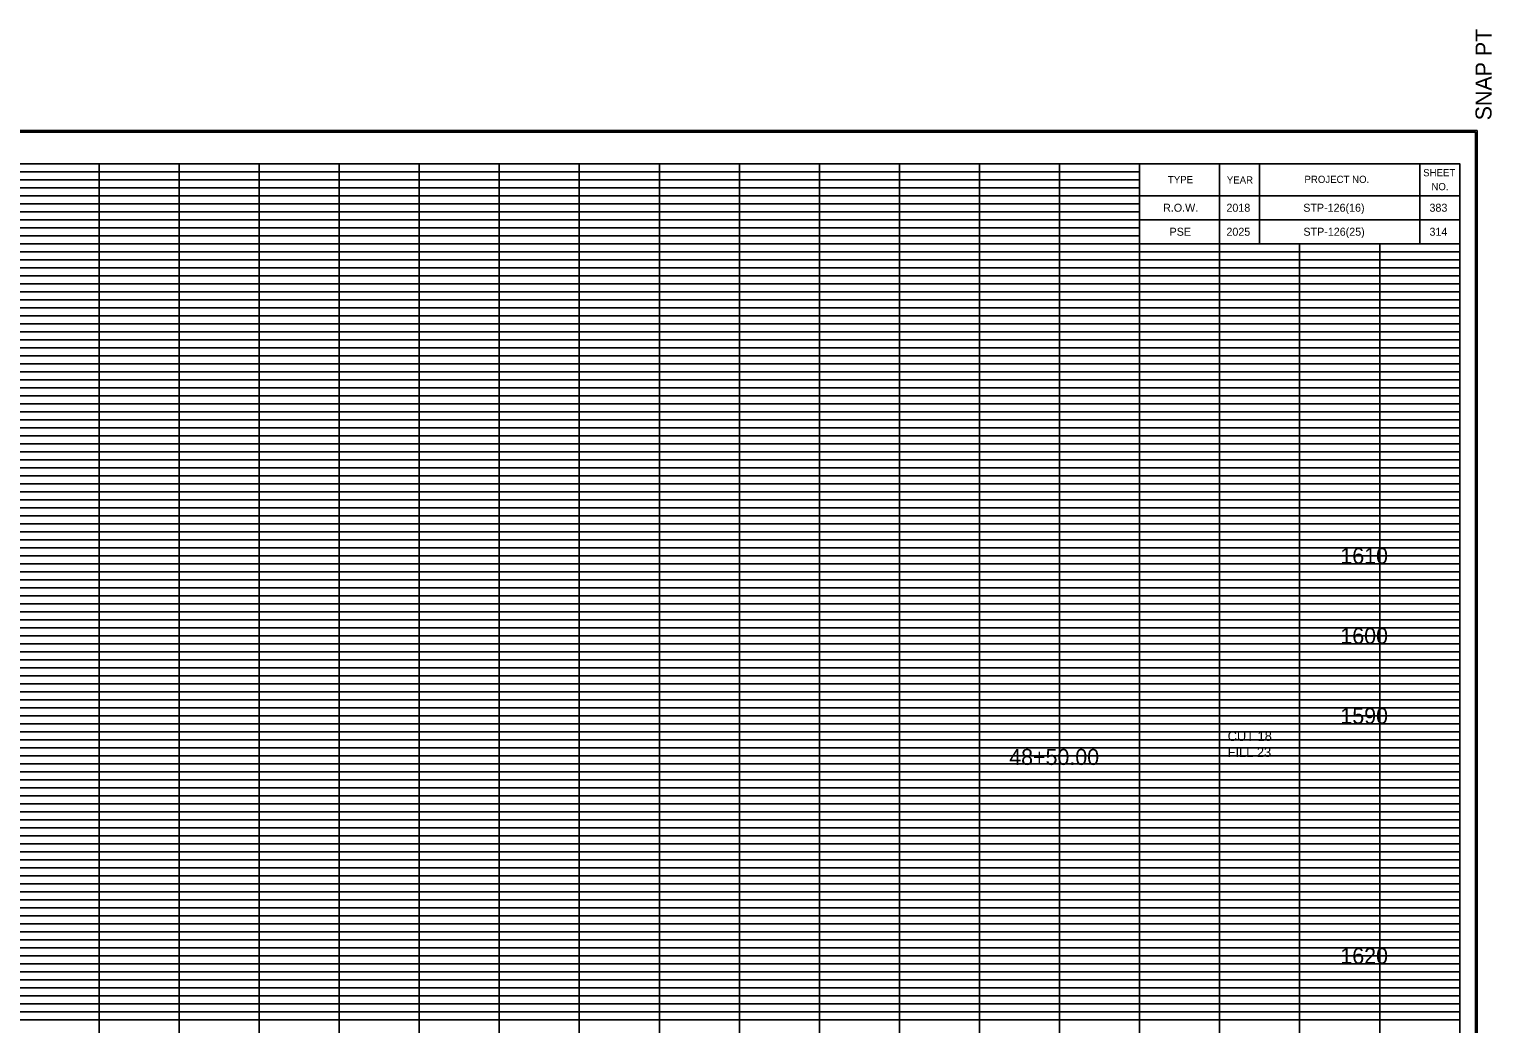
# Model space of a CAD drawing. Extents: x 980 to 1324, y 978 to 1497.
# Drawn here: x 1141.3 to 1324, y 1102.5 to 1226.8 of the extents above; entities that cross this region are included whole.
import ezdxf

# ---------------------------------------------------------------- set-up
doc = ezdxf.new("R2010")
doc.units = 0
for name, color, linetype in [('DESIGN - SCRATCH - User 1', 7, 'Continuous'), ('DESIGN - SHEET - Corner Text', 7, 'Continuous'), ('DESIGN - SHEET - Light Grid', 7, 'Continuous'), ('DESIGN - SHEET - Linework', 7, 'Continuous'), ('DESIGN - SHEET - Plot Shape', 7, 'Continuous'), ('DESIGN - TYPICAL - Text', 7, 'Continuous')]:
    doc.layers.add(name, color=color, linetype=linetype)

# ---------------------------------------------------------------- blocks, each defined once
blk = doc.blocks.new('XSTSHT')
at = {"layer": 'DESIGN - SCRATCH - User 1'}
for p, q in [((28.5, 20.45), (28.5, 20.45)), ((29.24, 20.45), (29.24, 20.45)), ((30.49, 20.45), (30.49, 20.45)), ((31.74, 20.45), (31.74, 20.45)), ((28.5, 20.15), (28.5, 20.15)), ((29.24, 20.15), (29.24, 20.15)), ((30.49, 20.15), (30.49, 20.15)), ((31.74, 20.15), (31.74, 20.15))]:
    blk.add_line(p, q, dxfattribs=at)
at = {"layer": 'DESIGN - SHEET - Light Grid'}
for p, q in [((8, 20.9), (16, 20.9)), ((16, 20.9), (24, 20.9)), ((24, 20.9), (28, 20.9)), ((8, 20.8), (16, 20.8)), ((8, 20.7), (16, 20.7)), ((16, 20.8), (24, 20.8)), ((16, 20.7), (24, 20.7)), ((24, 20.8), (28, 20.8)), ((24, 20.7), (28, 20.7)), ((8, 20.6), (16, 20.6)), ((8, 20.5), (16, 20.5)), ((16, 20.6), (24, 20.6)), ((16, 20.5), (24, 20.5)), ((24, 20.6), (28, 20.6)), ((24, 20.5), (28, 20.5)), ((8, 20.4), (16, 20.4)), ((8, 20.3), (16, 20.3)), ((16, 20.4), (24, 20.4)), ((16, 20.3), (24, 20.3)), ((24, 20.4), (28, 20.4)), ((24, 20.3), (28, 20.3)), ((8, 20.2), (16, 20.2)), ((8, 20.1), (16, 20.1)), ((16, 20.2), (24, 20.2)), ((16, 20.1), (24, 20.1)), ((24, 20.2), (28, 20.2)), ((24, 20.1), (28, 20.1)), ((8, 19.9), (16, 19.9)), ((8, 19.8), (16, 19.8)), ((16, 19.9), (24, 19.9)), ((16, 19.8), (24, 19.8)), ((24, 19.9), (32, 19.9)), ((24, 19.8), (32, 19.8)), ((8, 19.7), (16, 19.7)), ((8, 19.6), (16, 19.6)), ((16, 19.7), (24, 19.7)), ((16, 19.6), (24, 19.6)), ((24, 19.7), (32, 19.7)), ((24, 19.6), (32, 19.6)), ((8, 19.5), (16, 19.5)), ((8, 19.4), (16, 19.4)), ((16, 19.5), (24, 19.5)), ((16, 19.4), (24, 19.4)), ((24, 19.5), (32, 19.5)), ((24, 19.4), (32, 19.4)), ((8, 19.3), (16, 19.3)), ((8, 19.2), (16, 19.2)), ((16, 19.3), (24, 19.3)), ((16, 19.2), (24, 19.2)), ((24, 19.3), (32, 19.3)), ((24, 19.2), (32, 19.2)), ((8, 19.1), (16, 19.1)), ((16, 19.1), (24, 19.1)), ((24, 19.1), (32, 19.1)), ((8, 18.9), (16, 18.9)), ((16, 18.9), (24, 18.9)), ((24, 18.9), (32, 18.9)), ((8, 18.8), (16, 18.8)), ((8, 18.7), (16, 18.7)), ((16, 18.8), (24, 18.8)), ((16, 18.7), (24, 18.7)), ((24, 18.8), (32, 18.8)), ((24, 18.7), (32, 18.7)), ((8, 18.6), (16, 18.6)), ((8, 18.5), (16, 18.5)), ((16, 18.6), (24, 18.6)), ((16, 18.5), (24, 18.5)), ((24, 18.6), (32, 18.6)), ((24, 18.5), (32, 18.5)), ((8, 18.4), (16, 18.4)), ((8, 18.3), (16, 18.3)), ((16, 18.4), (24, 18.4)), ((16, 18.3), (24, 18.3)), ((24, 18.4), (32, 18.4)), ((24, 18.3), (32, 18.3)), ((8, 18.2), (16, 18.2)), ((8, 18.1), (16, 18.1)), ((16, 18.2), (24, 18.2)), ((16, 18.1), (24, 18.1)), ((24, 18.2), (32, 18.2)), ((24, 18.1), (32, 18.1)), ((8, 17.9), (16, 17.9)), ((8, 17.8), (16, 17.8)), ((16, 17.9), (24, 17.9)), ((16, 17.8), (24, 17.8)), ((24, 17.9), (32, 17.9)), ((24, 17.8), (32, 17.8)), ((8, 17.7), (16, 17.7)), ((8, 17.6), (16, 17.6)), ((16, 17.7), (24, 17.7)), ((16, 17.6), (24, 17.6)), ((24, 17.7), (32, 17.7)), ((24, 17.6), (32, 17.6)), ((8, 17.5), (16, 17.5)), ((8, 17.4), (16, 17.4)), ((16, 17.5), (24, 17.5)), ((16, 17.4), (24, 17.4)), ((24, 17.5), (32, 17.5)), ((24, 17.4), (32, 17.4)), ((8, 17.3), (16, 17.3)), ((8, 17.2), (16, 17.2)), ((16, 17.3), (24, 17.3)), ((16, 17.2), (24, 17.2)), ((24, 17.3), (32, 17.3)), ((24, 17.2), (32, 17.2)), ((8, 17.1), (16, 17.1)), ((16, 17.1), (24, 17.1)), ((24, 17.1), (32, 17.1)), ((8, 16.9), (16, 16.9)), ((16, 16.9), (24, 16.9)), ((24, 16.9), (32, 16.9)), ((8, 16.8), (16, 16.8)), ((8, 16.7), (16, 16.7)), ((16, 16.8), (24, 16.8)), ((16, 16.7), (24, 16.7)), ((24, 16.8), (32, 16.8)), ((24, 16.7), (32, 16.7)), ((8, 16.6), (16, 16.6)), ((8, 16.5), (16, 16.5)), ((16, 16.6), (24, 16.6)), ((16, 16.5), (24, 16.5)), ((24, 16.6), (32, 16.6)), ((24, 16.5), (32, 16.5)), ((8, 16.4), (16, 16.4)), ((8, 16.3), (16, 16.3)), ((16, 16.4), (24, 16.4)), ((16, 16.3), (24, 16.3)), ((24, 16.4), (32, 16.4)), ((24, 16.3), (32, 16.3)), ((8, 16.2), (16, 16.2)), ((8, 16.1), (16, 16.1)), ((16, 16.2), (24, 16.2)), ((16, 16.1), (24, 16.1)), ((24, 16.2), (32, 16.2)), ((24, 16.1), (32, 16.1)), ((8, 15.9), (16, 15.9)), ((16, 15.9), (24, 15.9)), ((24, 15.9), (32, 15.9)), ((8, 15.8), (16, 15.8)), ((16, 15.8), (24, 15.8)), ((24, 15.8), (32, 15.8)), ((8, 15.7), (16, 15.7)), ((8, 15.6), (16, 15.6)), ((16, 15.7), (24, 15.7)), ((16, 15.6), (24, 15.6)), ((24, 15.7), (32, 15.7)), ((24, 15.6), (32, 15.6)), ((8, 15.5), (16, 15.5)), ((8, 15.4), (16, 15.4)), ((16, 15.5), (24, 15.5)), ((16, 15.4), (24, 15.4)), ((24, 15.5), (32, 15.5)), ((24, 15.4), (32, 15.4)), ((8, 15.3), (16, 15.3)), ((8, 15.2), (16, 15.2)), ((16, 15.3), (24, 15.3)), ((16, 15.2), (24, 15.2)), ((24, 15.3), (32, 15.3)), ((24, 15.2), (32, 15.2)), ((8, 15.1), (16, 15.1)), ((16, 15.1), (24, 15.1)), ((24, 15.1), (32, 15.1)), ((8, 14.9), (16, 14.9)), ((16, 14.9), (24, 14.9)), ((24, 14.9), (32, 14.9)), ((8, 14.8), (16, 14.8)), ((8, 14.7), (16, 14.7)), ((16, 14.8), (24, 14.8)), ((16, 14.7), (24, 14.7)), ((24, 14.8), (32, 14.8)), ((24, 14.7), (32, 14.7)), ((8, 14.6), (16, 14.6)), ((8, 14.5), (16, 14.5)), ((16, 14.6), (24, 14.6)), ((16, 14.5), (24, 14.5)), ((24, 14.6), (32, 14.6)), ((24, 14.5), (32, 14.5)), ((8, 14.4), (16, 14.4)), ((8, 14.3), (16, 14.3)), ((16, 14.4), (24, 14.4)), ((16, 14.3), (24, 14.3)), ((24, 14.4), (32, 14.4)), ((24, 14.3), (32, 14.3)), ((8, 14.2), (16, 14.2)), ((8, 14.1), (16, 14.1)), ((16, 14.2), (24, 14.2)), ((16, 14.1), (24, 14.1)), ((24, 14.2), (32, 14.2)), ((24, 14.1), (32, 14.1)), ((8, 13.9), (16, 13.9)), ((16, 13.9), (24, 13.9)), ((24, 13.9), (32, 13.9)), ((8, 13.8), (16, 13.8)), ((16, 13.8), (24, 13.8)), ((24, 13.8), (32, 13.8)), ((8, 13.7), (16, 13.7)), ((8, 13.6), (16, 13.6)), ((16, 13.7), (24, 13.7)), ((16, 13.6), (24, 13.6)), ((24, 13.7), (32, 13.7)), ((24, 13.6), (32, 13.6)), ((8, 13.5), (16, 13.5)), ((8, 13.4), (16, 13.4)), ((16, 13.5), (24, 13.5)), ((16, 13.4), (24, 13.4)), ((24, 13.5), (32, 13.5)), ((24, 13.4), (32, 13.4)), ((8, 13.3), (16, 13.3)), ((8, 13.2), (16, 13.2)), ((16, 13.3), (24, 13.3)), ((16, 13.2), (24, 13.2)), ((24, 13.3), (32, 13.3)), ((24, 13.2), (32, 13.2)), ((8, 13.1), (16, 13.1)), ((16, 13.1), (24, 13.1)), ((24, 13.1), (32, 13.1)), ((8, 12.9), (16, 12.9)), ((8, 12.8), (16, 12.8)), ((16, 12.9), (24, 12.9)), ((16, 12.8), (24, 12.8)), ((24, 12.9), (32, 12.9)), ((24, 12.8), (32, 12.8)), ((8, 12.7), (16, 12.7)), ((16, 12.7), (24, 12.7)), ((24, 12.7), (32, 12.7)), ((8, 12.6), (16, 12.6)), ((8, 12.5), (16, 12.5)), ((16, 12.6), (24, 12.6)), ((16, 12.5), (24, 12.5)), ((24, 12.6), (32, 12.6)), ((24, 12.5), (32, 12.5)), ((8, 12.4), (16, 12.4)), ((8, 12.3), (16, 12.3)), ((16, 12.4), (24, 12.4)), ((16, 12.3), (24, 12.3)), ((24, 12.4), (32, 12.4)), ((24, 12.3), (32, 12.3)), ((8, 12.2), (16, 12.2)), ((8, 12.1), (16, 12.1)), ((16, 12.2), (24, 12.2)), ((16, 12.1), (24, 12.1)), ((24, 12.2), (32, 12.2)), ((24, 12.1), (32, 12.1)), ((8, 11.9), (16, 11.9)), ((16, 11.9), (24, 11.9)), ((24, 11.9), (32, 11.9)), ((8, 11.8), (16, 11.8)), ((8, 11.7), (16, 11.7)), ((16, 11.8), (24, 11.8)), ((16, 11.7), (24, 11.7)), ((24, 11.8), (32, 11.8)), ((24, 11.7), (32, 11.7)), ((8, 11.6), (16, 11.6)), ((16, 11.6), (24, 11.6)), ((24, 11.6), (32, 11.6)), ((8, 11.5), (16, 11.5)), ((8, 11.4), (16, 11.4)), ((16, 11.5), (24, 11.5)), ((16, 11.4), (24, 11.4)), ((24, 11.5), (32, 11.5)), ((24, 11.4), (32, 11.4)), ((8, 11.3), (16, 11.3)), ((8, 11.2), (16, 11.2)), ((16, 11.3), (24, 11.3)), ((16, 11.2), (24, 11.2)), ((24, 11.3), (32, 11.3)), ((24, 11.2), (32, 11.2)), ((8, 11.1), (16, 11.1)), ((16, 11.1), (24, 11.1)), ((24, 11.1), (32, 11.1)), ((8, 10.9), (16, 10.9)), ((8, 10.8), (16, 10.8)), ((16, 10.9), (24, 10.9)), ((16, 10.8), (24, 10.8)), ((24, 10.9), (32, 10.9)), ((24, 10.8), (32, 10.8)), ((8, 10.7), (16, 10.7)), ((8, 10.6), (16, 10.6)), ((16, 10.7), (24, 10.7)), ((16, 10.6), (24, 10.6)), ((24, 10.7), (32, 10.7)), ((24, 10.6), (32, 10.6)), ((8, 10.5), (16, 10.5)), ((16, 10.5), (24, 10.5)), ((24, 10.5), (32, 10.5)), ((8, 10.4), (16, 10.4)), ((8, 10.3), (16, 10.3)), ((16, 10.4), (24, 10.4)), ((16, 10.3), (24, 10.3)), ((24, 10.4), (32, 10.4)), ((24, 10.3), (32, 10.3))]:
    blk.add_line(p, q, dxfattribs=at)
at = {"layer": 'DESIGN - SHEET - Linework'}
for p, q in [((-1.823, 21.414), (32.217, 21.414)), ((32.217, 21.414), (32.217, -0.414)), ((15, 0), (15, 21)), ((16, 0), (16, 21)), ((17, 0), (17, 21)), ((18, 0), (18, 21)), ((19, 0), (19, 21)), ((20, 0), (20, 21)), ((21, 0), (21, 21)), ((22, 0), (22, 21)), ((23, 0), (23, 21)), ((24, 0), (24, 21)), ((25, 0), (25, 21)), ((26, 0), (26, 21)), ((27, 0), (27, 21)), ((0, 20), (28, 20)), ((28, 0), (28, 20)), ((29, 0), (29, 20)), ((30, 0), (30, 20)), ((31, 0), (31, 20)), ((0, 19), (32, 19)), ((0, 18), (32, 18)), ((0, 17), (32, 17)), ((0, 16), (32, 16)), ((0, 15), (32, 15)), ((0, 14), (32, 14)), ((0, 13), (32, 13)), ((0, 12), (32, 12)), ((0, 11), (32, 11))]:
    blk.add_line(p, q, dxfattribs=at)
for points in [[(0, 21), (0, 0), (32, 0), (32, 21), (0, 21)], [(28, 21), (28, 20), (32, 20), (32, 21), (31.5, 21), (31.5, 20), (29.5, 20), (29.5, 21), (29, 21), (29, 20), (32, 20), (28, 20), (28, 20.3), (32, 20.3), (32, 20.6), (28, 20.6)]]:
    blk.add_lwpolyline(points, dxfattribs=at)
at = {"layer": 'DESIGN - SHEET - Plot Shape'}
for points in [[(-1.803, 21.394), (32.197, 21.394), (32.197, -0.394), (-1.803, -0.394)], [(-0.85, 21), (32, 21), (32, -0.25), (-0.85, -0.25)]]:
    blk.add_lwpolyline(points, close=True, dxfattribs=at)
at = {"layer": 'DESIGN - SHEET - Corner Text'}
blk.add_text('  SNAP PT', height=0.2, rotation=90, dxfattribs=at).set_placement((32.397, 21.394))
for s, p in [('TYPE', (28.354, 20.756)), ('YEAR', (29.09, 20.752)), ('PROJECT NO.', (30.06, 20.76)), ('SHEET', (31.543, 20.843)), ('NO.', (31.646, 20.669))]:
    blk.add_text(s, height=0.09, dxfattribs=at).set_placement(p)

msp = doc.modelspace()

# ---------------------------------------------------------------- linework, layer by layer
at = {"layer": 'DESIGN - SHEET - Plot Shape'}
msp.add_lwpolyline([(991.5, 997.5), (1320, 997.5), (1320, 1210), (991.5, 1210)], close=True, dxfattribs=at)

# ---------------------------------------------------------------- block references
at = {"layer": 'DESIGN - TYPICAL - Text', "xscale": 10, "yscale": 10}
msp.add_blockref('XSTSHT', (1000, 1000), dxfattribs=at)

# ---------------------------------------------------------------- texts
at = {"layer": 'DESIGN - SHEET - Corner Text'}
for s, p in [('R.O.W.', (1282.94, 1204)), ('2018', (1290.85, 1204)), ('STP-126(16)', (1300.45, 1204)), ('383', (1316.22, 1204)), ('PSE', (1283.75, 1201)), ('2025', (1290.85, 1201)), ('STP-126(25)', (1300.47, 1201)), ('314', (1316.22, 1201))]:
    msp.add_text(s, height=1, dxfattribs=at).set_placement(p)
at = {"layer": 'DESIGN - TYPICAL - Text'}
for s, height, p in [('     1610     ', 2, (1301.37, 1160)), ('     1600     ', 2, (1301.37, 1150)), ('     1590     ', 2, (1301.37, 1140)), ('CUT 18', 1.2, (1291, 1137.86)), ('     48+50.00     ', 2, (1260, 1134.86)), ('FILL 23', 1.2, (1291, 1135.86)), ('     1620     ', 2, (1301.37, 1110))]:
    msp.add_text(s, height=height, dxfattribs=at).set_placement(p)

doc.saveas('drawing.dxf')
